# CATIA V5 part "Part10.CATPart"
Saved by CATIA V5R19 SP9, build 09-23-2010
Part number: Part10
Bounding box of the stored display mesh (mm): x -64.203 to 172.027, y 0 to 134.641, z -20 to 20
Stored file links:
  C:\Users\schwarz_maximilian\Desktop\Part10.CATPart

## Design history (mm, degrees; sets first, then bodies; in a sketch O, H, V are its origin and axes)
AxisSystem1: origin (0, 0, 0), X (1, 0, 0), Y (0, 1, 0), Z (0, 0, 1)
Set1 "Konstruktion"
  Sketch1 on XY plane of AxisSystem1, origin (0, 0, 0), H (1, 0, 0), V (0, 1, 0)
    spline S1 through (0, 0) (-3, 69) (79, 77) (172, 117) (62, 117) (-54, 98) (-49, 34) (-48, 34)
    point P1 (0, 0)
    coincidence: P1 O
  CLDGeom1 "Kurven diskretisieren.1"
  CLDGeom2 "123_Kurven diskretisieren.1_1.1"
  Point1: (81.4, 77.4, 0), in AxisSystem1
  Point2: (75.6, 76.5, 0), in AxisSystem1
  Point3: (69.8, 75.7, 0), in AxisSystem1
  Point4: (64, 75.1, 0), in AxisSystem1
  Point5: (58.1, 74.7, 0), in AxisSystem1
  Point6: (52.3, 74.3, 0), in AxisSystem1
  Point7: (46.4, 74.1, 0), in AxisSystem1
  Point8: (40.6, 74, 0), in AxisSystem1
  Line1: type PtPt, FirstPoint Point8, SecondPoint Point1
  Point9: type Between, FirstPoint Point1, SecondPoint Point8, Ratio 0.5
  Circle1: type CtrRad, Start 0, End 180, Radius 20, Center Point9, Support {plane type Normal, Curve Line1, RefPoint Point9}, FirstDirection (-0.083, 0.9965, 0)
  CLDGeom3 "Kurven diskretisieren.2"
  CLDGeom4 "123_Kurven diskretisieren.2_1.1"
Body1 (main body)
